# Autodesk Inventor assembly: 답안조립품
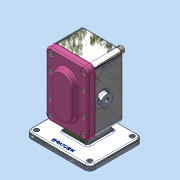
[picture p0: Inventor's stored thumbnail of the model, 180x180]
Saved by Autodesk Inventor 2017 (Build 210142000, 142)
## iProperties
Part Number: 답안조립품
Material: 일반
Document SubType Name: Assembly
Designer: MRC
Author: MRC
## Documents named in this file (11)
- C:\Users\MRC\Desktop\700407V1043\답안조립품.iam
- C:\Users\MRC\Desktop\700407V1043\본체.ipt
- C:\Users\MRC\Desktop\700407V1043\Ű 6 x 6 x 18.ipt
- C:\Users\MRC\Desktop\700407V1043\개스킷.ipt
- C:\Users\MRC\Desktop\700407V1043\메인축.ipt
- C:\Users\MRC\Desktop\700407V1043\베어링부시.ipt
- C:\Users\MRC\Desktop\700407V1043\볼트 M5.ipt
- C:\Users\MRC\Desktop\700407V1043\서브축.ipt
- C:\Users\MRC\Desktop\700407V1043\스퍼기어.ipt
- C:\Users\MRC\Desktop\700407V1043\오일 실 16 28 7.ipt
- C:\Users\MRC\Desktop\700407V1043\커버.ipt
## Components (3 placed, 2 different names)
1. Ű 6 x 6 x 18:1
2. 개스킷:1
3. Ű 6 x 6 x 18:2
